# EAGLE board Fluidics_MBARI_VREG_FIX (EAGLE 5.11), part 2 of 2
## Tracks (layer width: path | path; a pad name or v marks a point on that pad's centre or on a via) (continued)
N$52 (continued)
  Top 0.254: R12.1 101.9,63.96 102.55,64.6 103.5,64.6 | 103.82,64.6 IC9.9 103.5,64.6 | R14.2 105.71,64.91 105.41,64.6 103.5,64.6
N$56
  Bottom 0.61: IC1.8 113.86,14.33 115.56,16.03 118.74,16.03 119.69,15.08
  Bottom 1.016: Q4.3 119.69,15.08 120.96,16.35 R81.2
N$57
  Bottom 0.406: C11.2 118.11,32.22
  Bottom 0.61: C11.2 116.84,32.22 116.2,32.86 IC2.8 | D4.1 118.74,29.36 117.79,30.32 117.79,31.9 118.11,32.22
  Bottom 1.27: L3.P$1 113.34,34.44 IC2.8
N$58
  Bottom 0.254: IC4.13 93.02,31.9 93.01,31.89 C3.1
  Bottom 0.406: C3.1 93.02,29.05 93.02,28.09 94.93,26.19 R1.1
N$59
  Bottom 0.305: C1.2 109.53,16.98 107.95,15.39 IC1.5
N$60
  Bottom 0.305: R82.1 105.72,9.68 106.68,8.73 107.95,8.73 IC1.4
N$61
  Bottom 0.254: 130.82,38.56 LED.2
  Bottom 0.305: R0.1 130.82,38.56
N$62
  Bottom 0.305: C11.1 120.33,32.22 120.96,32.86 IC2.1
N$63
  Bottom 0.254: IC12.4 128.9,5.55 128.27,6.18 128.27,7.46 128.9,8.09 | 128.9,8.09 IC12.2 | 128.9,8.09 128.15,8.84 128.27,10.31 129.42,11.47 R49.2 129.47,13.42 129.22,13.81 129.22,16.98 130.17,17.62 130.17,26.51 133.32,29.66 Q8.3
N$64  (via drill 0.61)
  Top 0.254: 140.01,12.22 v138.43,12.22
  Top 0.305: 140.01,12.22 141.28,10.95 v141.28,8.09
  Bottom 0.254: IC11.4 140.01,5.55 140.65,6.18 140.65,7.46 | 140.65,7.46 140.01,8.09 IC11.2 | 140.65,7.46 v141.28,8.09 | 140.39,16.73 140.33,27.78 139.44,28.66 Q9.3
  Bottom 0.305: R48.2 138.17,12.47 v138.43,12.22 138.43,14.76 140.39,16.73
N$66
  Top 0.254: IC7.1 120.33,85.88 C13.2
  Bottom 0.254: C13.2 118.42,86.19 119.69,84.92 119.69,81.75 119.06,81.11 R52.2 119.69,74.45 120.31,75.07 R61.1
N$68
  Top 0.254: IC7.2 120.33,84.61 C13.1 116.84,84.29 R60.1
N$70
  Bottom 0.254: IC5.11 137.16,39.2 139.38,41.43 139.38,42.38 140.01,43.02 | 141.92,43.02 IC5.1 140.01,43.02 | R50.2 140.32,43.32 140.01,43.02
N$71  (via drill 0.61)
  Top 0.254: R59.2 117.47,80.48 114.93,83.02 v114.93,85.24 | IC8.6 111.76,83.02 113.98,85.24 v114.93,85.24 | v114.93,85.24 114.93,85.56 115.55,86.18 R60.2 116.84,90 117.15,90.32 R57.1
N$72
  Top 0.254: IC7.14 129.53,85.88 130.16,86.5 R56.1 130.81,86.51 130.82,86.5 C28.2 133.68,86.5 134.62,85.56 134.62,82.7 R55.2
  Bottom 0.254: R65.1 133.65,81.74 R55.2
N$73
  Top 0.254: 128.27,84.61 IC7.13 | 128.27,84.61 130.81,84.61 | 130.81,84.61 R56.2 | C28.1 130.82,84.62 130.81,84.61 | C27.2 129.22,90 126.36,87.15 126.36,85.24 127,84.61 128.27,84.61
N$74
  Top 0.254: R57.2 120.65,90.32 120.96,90 C27.1
N$75
  Top 0.254: IC7.6 121.28,79.53 120.98,79.83 R58.2 119.68,79.83 117.47,77.62 R59.1
N$77
  Bottom 0.61: D21.2 Q32.3
N$78
  Bottom 0.254: Q31.3 47.94,37.94 47.3,37.3 47.3,36.03
  Bottom 0.406: 47.3,36.03 R116.2 47,34.43 47.3,34.12 47.13,33.95 Q32.1
N$79
  Bottom 0.254: Q31.1 R115.1 48.27,44.29 50.48,44.29 51.43,43.33 51.43,43.02 C34.-
N$80
  Bottom 0.61: D25.2 44.45,29.05 42.86,30.63 Q37.3
N$81
  Bottom 0.61: D24.2 Q36.3
N$82
  Bottom 0.254: Q35.3 37.78,37.94 37.14,37.3 37.14,36.03
  Bottom 0.406: 37.14,36.03 R119.2 36.84,34.43 37.14,34.12 36.97,33.95 Q36.1
N$83
  Bottom 0.254: Q35.1 R118.1 38.11,44.29 40.32,44.29 41.27,43.33 41.27,43.02 C35.-
N$84
  Bottom 0.61: D28.2 34.28,29.05 32.7,30.63 Q41.3
N$85
  Bottom 0.61: D27.2 Q40.3
N$86
  Bottom 0.254: Q39.3 27.62,37.94 26.98,37.3 26.98,36.03
  Bottom 0.406: 26.98,36.03 R122.2 26.68,34.43 26.98,34.12 26.81,33.95 Q40.1
N$87
  Bottom 0.254: Q39.1 R121.1 27.95,44.29 30.16,44.29 31.11,43.33 31.11,43.2 C36.-
N$88
  Top 0.61: D7.2 26.67,29.05 27.62,30 Q13.3
N$89
  Top 0.61: D6.2 Q12.3
N$90
  Top 0.254: Q11.3 33.8,38.11 33.97,37.94 33.97,36.03
  Top 0.406: 33.97,36.03 R101.2 33.64,33.81 33.65,33.81 | 33.65,33.81 | Q12.1 33.65,33.81
N$91
  Top 0.254: Q11.1 33.65,43.65 R100.1 32.37,44.92 30.16,44.92 28.89,43.65 C29.-
N$92
  Top 0.254: D30.1 68.58,58.26 67.04,56.72 R128.1
N$93B
  Top 0.254: U2.6 61.49,70.86 60.95,70.32 59.68,70.32 58.41,71.59 56.51,71.59 C47.1
N$95
  Top 0.254: R90.1 15.23,68.41 16.19,67.46 16.19,66.83 IC16.8
N$98
  Top 0.254: IC16.6 17.78,64.29 18.73,65.24 18.73,69.37 R91.1
N$99B
  Top 0.254: C42.+ 80.45,39.34 82.86,41.74 U5.2
N$100
  Top 0.61: D10.2 36.19,29.05 37.78,30.63 Q17.3
N$101B
  Top 0.254: U5.1 84.77,40.48 84.77,40.16 83.37,38.76 C41.+
N$102B
  Top 0.254: C41.- 86.17,38.7 86.36,38.89 86.36,42.38 85.72,43.02 U5.3
N$103B
  Top 0.254: C43.+ 87.44,41.3 86.99,41.74 86.99,43.65 86.36,44.29 U5.4
N$104B
  Top 0.254: C43.- 87.81,44.1 86.36,45.55 U5.5
N$106
  Top 0.254: IC15.1 23.17,66.83 23.17,67.78 23.81,68.41 R87.2
N$107
  Top 0.254: IC15.6 28.25,64.29 28.27,64.3 R88.1
N$108
  Top 0.61: D9.2 Q16.3
N$109
  Top 0.254: Q15.3 43.96,38.11 44.13,37.94 44.13,36.03
  Top 0.406: 44.13,36.03 R104.2 43.8,33.81 43.81,33.81 | 43.81,33.81 | Q16.1 43.81,33.81
N$110
  Top 0.254: Q15.1 43.81,43.65 R103.1 42.53,44.92 40.32,44.92 39.05,43.65 C30.-
N$111
  Top 0.61: D13.2 45.71,29.05 47.94,31.27
  Top 0.813: 47.94,31.27 Q21.3
N$112
  Top 0.61: D12.2 Q20.3
N$113
  Top 0.254: Q19.3 54.12,38.11 54.29,37.94 54.29,36.03
  Top 0.406: 54.29,36.03 R107.2 53.96,33.81 53.97,33.81 | 53.97,33.81 | Q20.1 53.97,33.81
N$114
  Top 0.254: Q19.1 53.97,43.65 R106.1 52.69,44.92 50.48,44.92 49.52,43.97 49.21,43.97 49.21,43.78 C31.-
N$115
  Top 0.61: D16.2 56.19,29.05 58.1,30.95
  Top 0.813: 58.1,30.95 Q25.3
N$116
  Top 0.61: D15.2 Q24.3
N$117
  Top 0.254: Q23.3 64.28,38.11 64.45,37.94 64.45,36.03
  Top 0.406: 64.45,36.03 R110.2 64.12,34.12 64.13,34.12 | 64.13,34.12 | Q24.1 64.13,34.12
N$118
  Top 0.254: Q23.1 64.13,43.65 R109.1 62.85,44.92 60.95,44.92 59.68,43.65 C32.-
N$122
  Bottom 0.254: R7.2 94.94,29.67 93.66,30.95 93.66,33.17 93.34,33.49
  Bottom 0.406: C3.2 91.13,30.01 91.75,30.63 IC4.14 91.75,33.17 92.07,33.49 93.34,33.49 93.34,35.4 93.02,35.71 IC4.2 93.02,37.62
N$132
  Bottom 0.254: IC4.12 94.29,34.12 | R4.2 99.69,40.48 100.01,40.79 99.68,41.12 C61.1
  Bottom 0.406: R4.2 99.68,38.88 99.37,38.57 IC4.7 99.37,34.76 98.1,33.49 IC4.9 98.1,33.81 97.47,34.44 94.61,34.44 94.29,34.12
N$133  (via drill 0.61)
  Top 0.406: v65.08,8.41 78.1,8.41 v89.85,20.16
  Bottom 0.254: Q6.1 64.76,8.73 v65.08,8.41
  Bottom 0.406: v89.85,20.16 89.85,32.22 91.75,34.44 IC4.1
N$134  (via drill 1.78)
  Bottom 1.27: Q5.2 71.12,15.71 72.54,17.14 | 72.54,17.14 72.7,17.3 L1.P$2 72.7,22.38 v73.66,23.33 | 72.54,17.14 | D2.C 73.66,16.03 72.54,17.14
N$135  (via drill 0.61)
  Top 0.254: v100.58,37.68 99.18,39.08 v96.64,39.08 96.64,39.01 95.23,37.61 C60.2
  Bottom 0.254: IC4.5 96.83,38.89 v96.64,39.08 | 101.59,36.79 101.47,36.79 v100.58,37.68
  Bottom 0.406: IC4.5 96.83,37.62 | R3.1 101.59,36.79 R2.2
N$136
  Bottom 0.254: R4.1 97.8,40.49 C61.2
  Bottom 0.406: R4.1 97.8,39.22 98.1,38.89 IC4.6
N$137
  Bottom 0.406: IC4.10 96.83,31.9 96.82,31.89 R7.1 R6.2
N$138
  Bottom 0.406: R8.1 93.67,39.51 94.29,38.89 IC4.3
N$143
  Bottom 0.254: R39.1 94.93,57.62 94.29,58.26 J2.2
N$144
  Bottom 0.254: 94.93,51.91 R39.2 | R39.2 | 94.93,51.91 95.56,51.27 IC6.2 95.56,50 | R40.1 92.07,50.63 93.34,51.91 94.93,51.91 | R83.2 96.83,58.26 96.2,57.62 96.2,53.49 95.88,53.18 R39.2
N$145
  Bottom 0.254: R43.1 97.16,52.87 97.15,52.86 | 97.15,52.86 R41.2 | IC6.3 96.83,52.54 97.15,52.86
N$146
  Bottom 0.254: R41.1 99.06,53.18 99.39,53.51 R42.1 101.59,52.54 102.55,51.59 J4.2
N$147
  Bottom 0.305: Q7.E 64.91,14.61 66.35,13.17 Q5.1 67,11.91 R5.2 66.35,7.77 65.72,7.14 62.22,7.14 60.95,8.09 D3.A
N$148
  Bottom 0.305: Q7.B 64.91,16.49 63.81,15.39 63.81,12.85 | 63.81,12.85 Q6.3 | 63.81,12.85 62.86,12.85 61.92,11.91 R44.2 60.33,11.91 56.51,8.09 D3.C
NVREF1
  Top 0.254: R89.1 21.26,60.17 24.76,56.67 R84.P$2
NVREF2
  Top 0.254: R92.1 10.14,60.17 13.33,56.98 R85.P$2
P
  Top 0.254: R17.2 129.87,71.58 129.53,71.91 R53.3
  Bottom 0.254: R63.2 127.63,72.86 126.68,71.91 | 125.09,71.91 R53.3 126.68,71.91 | R64.1 127.63,70.95 126.68,71.91
PGC  (via drill 0.61)
  Top 0.254: U1.52 50.27,55.6 v52.38,53.49
  Bottom 0.254: v52.38,53.49 52.7,53.81 54.6,53.81 55.56,52.86 67.62,52.86 69.84,50.95 69.84,46.51 J10.3
PGD  (via drill 0.61)
  Top 0.254: U1.47 51.27,58.1 v53.34,56.03
  Bottom 0.254: v53.34,56.03 53.65,55.72 57.14,55.72 59.37,53.49 67.94,53.49 71.12,50.95 71.12,48.09 J10.4
PIC_RS232_RX_A  (via drill 0.61)
  Top 0.254: 78.73,44.29 U5.13 v80.96,44.29 | v81.28,5.87 v81.28,8.41
  Bottom 0.254: J5.2 78.73,78.26 82.23,74.77 82.23,45.55 v80.96,44.29 80.96,42.7 81.59,42.06 81.59,10.31 81.28,10 v81.28,8.41 | v81.28,5.87 81.28,3.49 P3.34
PIC_RS232_RX_B  (via drill 0.61)
  Top 0.254: U5.8 84.77,49.37 84.77,50.95 v84.45,51.27
  Bottom 0.254: J3.2 88.26,88.42 89.21,87.46 89.21,81.75 84.13,76.67 84.13,51.59 v84.45,51.27
PIC_RS232_TX_A  (via drill 0.61)
  Top 0.254: 78.42,43.02 U5.14 v81.91,43.02 | v80.32,25.87 v82.55,25.87 | P3.33 v80.01,8.41
  Bottom 0.254: J5.3 81.28,87.78 80.01,86.51 80.01,78.26 83.18,75.08 83.18,44.29 v81.91,43.02 82.55,42.38 v82.55,25.87 | v80.32,25.87 80.32,8.73 v80.01,8.41
PIC_RS232_TX_B  (via drill 0.61)
  Top 0.254: 84.45,48.09 U5.7 v86.36,48.09
  Bottom 0.254: J3.3 90.8,88.42 90.17,87.78 90.17,81.11 85.09,76.03 85.09,52.22 85.72,51.59 85.72,48.73 v86.36,48.09
PID_OUT
  Top 0.254: 118.42,53.81 117.15,53.81 116.85,53.51 R20.1 115.56,53.81 117.15,52.22 119.06,52.22 | IC10.2 119.06,60.16 120.01,59.21 120.01,54.13 119.69,53.81 118.42,53.81 | 118.42,53.81 IC10.7 | R22.2 124.76,51.26 124.14,50.63 119.69,50.63 119.06,51.27 119.06,52.22 | 119.06,52.22 R24.2
PRES1_OUT
  Top 0.254: U3.11 38.36,75.66 38.09,75.4 38.09,75.08 30.79,67.78 30.79,66.18 R88.2
PRES2_OUT
  Top 0.254: U3.10 37.74,76.31 31.11,69.68 20.95,69.68 20.63,69.37 R91.2 20.62,69.06 20.63,69.05
PROP  (1 unrouted)
  Top 0.254: R53.2 125.09,74.45 122.61,76.92 IC7.7 121.28,78.26 120.98,77.95 R58.1 120.02,77.95 117.79,75.72 R129.1
  Bottom 0.254: R63.1 126.35,75.39 R53.2
PROP1  (via drill 0.6, 0.61)
  Top 0.254: 38.09,80.8 37.39,81.5 35.94,81.5 31.75,77.3 7.62,77.3 6.03,75.72 P1.53 | 38.09,80.8 U3.3 | v93.66,80.16 94.93,78.89 96.2,78.89 99.06,76.03 101.59,76.03 101.91,75.72 R129.2 113.36,76.36 114.61,77.62 C59.1 | v92.07,84.61 90.8,84.61 88.58,82.38 81.59,82.38 80.32,83.65 76.51,83.65 v72.07,79.21 | v36.51,86.83 v51.11,86.83 | v36.51,80.48 37.78,80.48 38.09,80.8
  Bottom 0.254: R67.1 5.71,75.72 P1.53 | v93.66,80.16 93.66,83.02 v92.07,84.61 | v72.07,79.21 61.91,79.21 60.64,77.94 54.29,77.94 51.11,81.11 v51.11,86.83 | v36.51,80.48 v36.51,86.83
PS_OUT1+
  Top 0.203: 9.24,66.69 9.75,66.18 12.39,66.18 14.93,63.64 20,63.64
  Top 0.254: IC15.3 20.63,64.29 20,63.65 20,63.64 R89.2 | 9.24,66.69 4.36,66.69 3.25,67.8 P1.48
PS_OUT1-
  Top 0.254: IC15.2 22.22,65.56 19.68,68.1 19.68,70.32 19.36,70.64 12.38,70.64 9.84,68.1 P1.47
PS_OUT2+
  Top 0.254: IC16.3 9.52,64.29 8.25,63.02 R92.2 8.25,62.38 6.34,64.29 3.81,64.29 P1.46
PS_OUT2-
  Top 0.254: P1.45 IC16.2
PVDD  (via drill 0.61)  (1 unrouted)
  Top 0.254: U1.71 51.68,50.57 v52.38,51.27 | U1.48 47.07,57.6 | v56.51,57.62 57.03,57.1 U1.12 58.93,57.1 59.68,56.35 | C50.1 47.3,76.35 47.4,76.25 C49.1 47.3,74.45 46.73,75.02 U3.17 | C50.1 47.4,77.2 46.35,78.26 45.08,78.26 45.09,78.27 U3.22 | U1.53 46.01,55.1 46.98,54.13 v46.98,53.18 | 63.49,56.35 63.43,56.29 C39.1 63.56,56.29 63.49,56.35 | 63.49,56.35 63.18,56.67 63.18,57.3 62.86,57.62 61.43,57.62 60.95,57.14 60.95,56.51 60.8,56.35 | 59.68,56.35 | 59.68,56.35 59.84,56.19 60.64,56.19 60.8,56.35 | 60.8,56.35 | D30.2 72,58.51 72,59.4 v71.75,59.84 | 47.06,57.57 47.29,57.44 v47.62,57.18 | v37.14,66.51 37.33,66.59 37.33,67.93 C51.1 37.45,68.11 37.46,68.1 37.67,68.3 U4.14 | C50.1 48,77 48,77.53 v48.25,77.94 51.43,77.94 52.38,76.99 52.38,75.4 53.02,74.77 53.97,74.77 54.6,75.4 IC13.2 | U1.25 54.18,64.18 v54.29,64.29 | v49.52,60.03 49.52,60.16 50.68,61.31 U1.32 | C25.1 55.56,74.13 54.6,75.08 IC13.2 | IC13.2 54.6,76.67 | 78.42,40.48 74.93,40.48 73.66,41.74 J10.2 | 78.42,40.48 U5.16 | C42.- 77.65,38.76 78.42,39.52 78.42,40.48 | R78.1 84.44,55.07 84.77,55.4 84.77,56.35 Q42.2 86.53,56.52 v86.99,56.98
  Top 0.61: J10.2 72,41.74 69.72,39.46 R38.1
  pvdd 0.254: J10.2 74.29,41.74
  Bottom 0.254: 75.56,39.84 C40.+ 75.06,39.71 73.02,41.74 J10.2 72.7,41.74 74.29,43.33 74.29,50.32 70.8,53.81 70.8,58.89 v71.75,59.84 | D34.1 35.55,63.65 37.14,65.24 v37.14,66.51
  pour pvdd (isolate 0.61): 54.6,78.26 36.51,78.26 36.51,43.65 32.38,43.33 68.26,43.33 71.12,46.19 73.97,46.19 73.97,39.52 71.43,39.52 71.43,37.3 88.58,37.3 88.58,63.02 77.47,63.02 77.15,62.7 54.6,62.7
PWM1_IN
  Top 0.254: R95.2 13.95,51.92 13.96,51.91 15.55,53.49 24.12,53.49 26.03,55.4 26.03,57.3 27.62,58.89 32.7,58.89 32.7,60.8 35.87,63.97 39.05,63.97 42.92,60.1 U1.43
PWM1_OUT
  Top 0.254: R95.1 12.07,52.84 11.42,53.49 9.2,53.49 | C53.1 8.67,52.12 8.57,52.22 8.88,52.54 8.88,53.18 9.2,53.49 | P1.38 3.81,56.67 6.98,56.67 9.2,54.45 9.2,53.49
PWM2_IN
  Top 0.254: U1.55 44.79,54.1 44.76,54.13 41.9,54.13 39.68,51.91 24.76,51.91 20.95,48.09 13.65,48.09 13.84,48.29 R96.2
PWM2_OUT
  Top 0.254: R96.1 12.07,47.79 11.42,47.14 9.2,47.14 8.57,47.78 8.57,48.09 8.67,48.2 C54.1 8.76,48.29 8.88,48.41 7.3,50 7.3,53.49 5.39,55.4 P1.37
PWM3_IN  (via drill 0.61)
  Top 0.254: U1.5 56.62,53.6 56.53,53.53 54.93,53.53 54.4,53 v53.97,52.86 | R97.2 16.44,36.92 v17.14,37.62
  Bottom 0.254: v17.14,37.62 17.27,37.74 17.27,38.82 20.19,41.74 22.22,41.74 26.67,46.19 44.13,46.19 50.62,52.69 50.67,52.64 53.69,52.64 v53.97,52.86
PWM3_OUT
  Top 0.254: 8.88,36.66 8.95,36.6 C55.1 | P1.34 2.22,50.32 1.33,49.56 1.33,39.27 1.71,38.89 6.98,38.89 8.95,36.92 C55.1 | C55.1 8.95,36.28 | R97.1 13.98,36.97 13.96,36.98 13.96,37.62 13.65,37.94 12.38,37.94 12.06,38.25 9.2,38.25 8.88,37.3 8.88,37.05 9.01,36.92 C55.1
PWM4_IN  (via drill 0.61)
  Top 0.254: U1.8 57.16,55.1 v56.51,54.45 | R98.2 16.19,43.65 v17.14,43.65
  Bottom 0.254: v56.51,54.45 51.11,54.45 43.49,46.83 24.76,46.83 21.59,43.65 v17.14,43.65
PWM4_OUT
  Top 0.254: 8.57,41.43 8.67,41.53 C56.1 | R98.1 12.07,41.12 11.11,40.16 9.2,40.16 8.88,40.48 8.88,41.43 8.76,41.55 C56.1 | C56.1 8.67,41.64 6.34,43.97 4.12,43.97 3.81,44.29 3.81,51.59 P1.35
PWM5_IN  (via drill 0.61)
  Top 0.254: U1.10 57.21,56.1 56.83,55.72 54.6,55.72 53.97,55.08 52.38,55.08 v52.06,55.4 | v18.73,44.92 18.25,44.73 14.41,44.73 13.96,44.92 14.02,44.87 R99.2
  Bottom 0.254: v18.73,44.92 20.32,44.92 22.86,47.46 42.22,47.46 42.31,47.48 42.49,47.48 47.82,52.82 47.82,53 50.13,55.31 50.16,55.4 v52.06,55.4
PWM5_OUT
  Top 0.254: R99.1 12.14,45.8 11.42,46.51 9.2,46.51 | 9.2,46.51 8.57,45.87 8.57,45.24 8.88,44.92 8.82,44.86 C57.1 | 9.2,46.51 6.98,46.51 6.34,47.14 6.34,53.49 5.71,54.13 3.81,54.13 P1.36
RB0
  Top 0.203: 15.87,33.81 20.95,38.89
  Top 0.254: U1.58 43.55,52.6 40.95,50 25.71,50 20.95,45.24 20.95,38.89 | 15.87,33.81 8.88,33.81 6.34,36.35 3.81,36.35 P1.24
RB1
  Top 0.203: 15.55,34.44 20.32,39.2
  Top 0.254: U1.57 43.1,53.1 40.63,50.63 25.39,50.63 20.32,45.55 20.32,39.2 | 15.55,34.44 9.52,34.44 6.66,37.3 5.39,37.3 P1.23
RB2
  Top 0.254: U1.56 42.65,53.6 40.32,51.27 25.08,51.27 19.68,45.87 19.68,42.38 16.19,38.89 7.93,38.89 6.66,40.16 P1.25
RB4
  Top 0.254: U1.54 41.11,54.6 39.36,52.86 29.84,52.86 29.52,52.54 17.78,52.54 15.23,50 13.65,50 13.01,49.37 13.01,40.16 12.38,39.52 8.25,39.52 6.34,41.43 3.49,41.43 2.54,40.48 P1.26
RC0  (via drill 0.61)
  Top 0.254: U1.36 48.68,62.17 47.94,61.43 v46.98,61.43
  Bottom 0.254: v46.98,61.43 43.81,58.26 40.63,58.26 39.68,57.3 33.02,57.3 28.25,52.54 7.62,52.54 6.34,51.27 6.34,49.05 P1.31
RC1  (via drill 0.61)
  Top 0.254: U1.35 49.18,61.46 v49.21,61.43
  Bottom 0.254: v49.21,61.43 48.89,61.11 48.25,61.11 47.62,60.48 46.98,60.48 42.86,56.35 34.6,56.35 29.84,51.59 13.01,51.59 10.47,49.05 8.88,49.05 6.34,46.51 3.81,46.51 P1.32
RD#
  Top 0.203: U1.27 53.18,64.77 53.65,65.24 54.92,65.24 55.63,64.54 U2.16
RESET#  (via drill 0.61)
  Top 0.254: U1.34 49.68,68.57 50,68.57 50.79,69.37 v51.75,69.37 | U2.4 63.17,71.59 63.18,71.59 63.18,70.64 62.86,70.32 62.86,70 62.22,70 v61.91,69.68
  Bottom 0.254: v61.91,69.68 60.64,69.68 60,69.05 52.06,69.05 v51.75,69.37
RH4  (via drill 0.61)
  Top 0.254: U1.22 55.68,61.55 55.65,61.53 55.29,61.18 v54.87,60.95
  Bottom 0.254: P1.29 6.66,45.24 9.52,48.09 14.28,48.09 17.14,50.95 31.43,50.95 36.19,55.72 43.17,55.72 46.35,58.89 50.16,58.89 51.11,59.84 52.38,59.84 53.34,60.82 54.4,60.82 v54.87,60.95
RH5  (via drill 0.61)
  Top 0.254: U1.21 57.07,62.95 v57.14,63.02
  Bottom 0.254: v57.14,63.02 56.83,62.7 56.83,61.43 55.24,59.84 53.97,59.84 53.34,59.21 52.06,59.21 51.11,58.26 47.3,58.26 46.98,57.94 46.35,57.94 41.27,52.86 35.55,52.86 32.7,50 18.73,50 15.23,46.51 8.88,46.51 6.34,43.97 3.81,43.97 P1.30
RH6  (via drill 0.61)
  Top 0.203: U1.20 56.81,61.1 56.51,60.8 56.51,60.48 54.6,58.57
  Top 0.254: v53.97,58.57 54.6,58.57
  Bottom 0.254: v53.97,58.57 53.02,58.57 51.75,57.3 49.02,57.3 48.89,57.11 47.49,55.72 47.11,55.72 43.17,51.59 36.19,51.59 33.97,49.37 19.36,49.37 14.92,44.92 8.88,44.92 6.66,42.7 P1.27
RH7  (via drill 0.61)
  Top 0.203: U1.19 56.95,60.6 56.95,59.65
  Top 0.254: v56.19,58.89 56.95,59.65
  Bottom 0.254: v56.19,58.89 54.29,56.98 52.7,56.98 52.38,56.67 49.21,56.67 43.49,50.95 36.51,50.95 34.28,48.73 20.63,48.73 13.33,41.43 3.49,41.43 2.54,42.38 P1.28
RJ0
  Top 0.203: U1.62 47.18,48.93 46.03,47.78 | 17.46,31.27 23.49,37.3
  Top 0.254: 46.03,47.78 27.3,47.78 23.49,43.97 23.49,37.3 | P1.20 2.99,32.5 3.74,31.43 3.96,31.43 4.12,31.27 17.46,31.27
RJ1
  Top 0.203: 45.77,48.35 46.65,49.24 U1.61 | 17.14,31.9 22.86,37.62
  Top 0.254: 45.77,48.35 26.92,48.35 22.86,44.29 22.86,37.62 | 17.14,31.9 5.71,31.9 P1.19
RJ2
  Top 0.203: 17.98,33.69 22.22,37.94
  Top 0.254: U1.60 44.39,51.6 41.68,48.88 26.5,48.88 22.22,44.6 22.22,37.94 | 17.98,33.69 17.98,33.67 17.95,33.67 16.82,32.54 7.62,32.54 6.34,33.81 4.44,33.81 3.17,35.08 P1.22
RJ3
  Top 0.203: 16.51,33.17 21.59,38.25
  Top 0.254: U1.59 43.99,52.08 41.27,49.37 26.03,49.37 21.59,44.92 21.59,38.25 | 16.51,33.17 7.93,33.17 6.34,34.76 5.39,34.76 P1.21
RSTOUT#
  Top 0.254: U2.5 62.29,72.15 60.95,73.49 R86.2
RXF#
  Top 0.203: U1.30 51.68,65.17 54.29,67.78 58.41,67.78
  Top 0.254: 58.41,67.78 58.45,67.75 U2.12
SER_RX2
  Top 0.254: R78.2 81.11,55.57 Q43.3 74.61,57.94 73.66,56.98 73.66,55.72 | 73.66,55.4 D5.2 73.66,55.72 | U1.7 70.95,54.6 72.07,55.72 73.66,55.72
SER_RX2B
  Top 0.254: U5.9 76.83,49.37 74.29,51.91 73.66,51.91 D5.1
SER_TX1  (via drill 0.61)
  Top 0.254: U1.37 48.18,63.9 49.21,64.92 49.21,67.46 49.17,67.5 49.17,69.02 50.29,70.14 v50.48,70.64 | U5.11 79.69,46.83 80.32,47.46 v80.32,50.95
  Bottom 0.254: v50.48,70.64 50.79,70.95 52.38,70.95 53.34,70 59.37,70 60.64,71.27 65.4,71.27 70.16,66.51 70.16,65.56 73.34,62.38 74.29,62.38 80.32,56.35 v80.32,50.95
SER_TX2  (via drill 0.61)
  Top 0.254: v75.56,48.09 U5.10 | U1.6 72.99,54.1 v75.56,54.13 79.69,54.13 81.28,52.54 82.86,52.54 83.5,52.86 83.5,55.08 82.87,55.71 Q42.1
  Bottom 0.254: 75.56,47.78 v75.56,48.09 v75.56,54.13
SG  (via drill 0.61)
  Top 0.254: U1.38 47.68,64.98 v48.25,65.56 | U5.12 80.01,45.55 v81.28,46.83
  Bottom 0.254: v48.25,65.56 48.57,65.56 51.43,68.41 60.95,68.41 62.22,67.14 66.04,67.14 79.05,54.45 79.05,51.91 79.05,49.05 v81.28,46.83
SI/WU
  Top 0.254: 50.18,63 50.16,63.02 | U1.33 50.18,63 | 50.18,63 50.18,64.62 54.09,68.54 U2.11
SPI_CLK  (via drill 0.61)
  Top 0.254: v40.63,70.95 40.58,70.9 U4.10 38.46,70.9 38.09,71.27 38.09,72.22 38.41,72.54 41.9,72.54 43.73,74.36 U3.16 | U1.44 42.15,59.6 v41.27,60.48
  Bottom 0.254: v40.63,70.95 41.59,70 41.59,64.92 44.13,62.38 44.13,61.43 43.17,60.48 v41.27,60.48
SPI_PIC_DIN  (via drill 0.61)
  Top 0.254: U1.45 45.61,59.1 46.03,59.52 46.03,62.7 43.17,65.56 v43.17,65.88 | U3.15 45.12,72.9 44.45,72.22 43.17,72.22 v42.86,71.91
  Bottom 0.254: v42.86,71.91 42.54,71.59 42.54,66.51 v43.17,65.88
SPI_PIC_DOUT  (via drill 0.61)
  Top 0.203: 37.84,70.25 U4.11
  Top 0.254: U3.19 45.08,76.35 44.45,76.35 41.27,73.18 38.09,73.18 37.46,72.54 37.46,71.27 v37.14,70.95 37.84,70.25 | U1.46 43.84,58.6 43.49,58.26 42.22,58.26 39.36,61.11 39.36,62.38 v39.05,62.7
  Bottom 0.254: v39.05,62.7 38.41,63.34 38.41,64.6 38.35,64.6 38.35,69.81 38.29,69.81 v37.14,70.95
SW1_NEG
  Bottom 0.406: 11.74,7.77 10.79,6.82 10.79,6.5 10.15,5.87 D31.2
  Bottom 0.813: Q1.2 13.65,5.87 11.74,7.77 9.84,9.68 P1.1
SW2_NEG
  Bottom 0.406: 23.17,10.95 3.81,10.95 P1.2 | 21.27,5.23 D32.2 25.08,5.23
  Bottom 0.813: Q2.2 25.08,5.23 25.08,9.04 23.17,10.95
SW3_NEG
  Bottom 0.406: 36.51,5.23 D33.2
  Bottom 0.813: Q3.2 36.51,5.23 36.51,7.46 31.75,12.22 P1.3
TC_SETPOINT  (via drill 0.61)
  Top 0.254: U3.12 40.25,75.02 v40.63,75.4 | J6.2 79.05,70.32 78.42,70.95 v78.42,73.81
  Bottom 0.254: v40.63,75.4 51.11,75.4 53.34,73.18 55.24,73.18 57.14,75.08 77.47,75.08 v78.42,73.81
TC_SETPOINT_SET  (via drill 0.61)
  Top 0.254: U4.2 45.84,67.65 46.35,67.14 46.35,66.83 45.71,66.19 v45.71,64.92 | R19.2 84.45,74.77 82.55,72.86 J6.3
  Bottom 0.254: v45.71,64.92 45.71,67.14 46.35,67.78 47.62,67.78 48.89,69.05 48.89,71.59 49.52,72.22 52.38,72.22 53.34,71.27 59.37,71.27 60.32,72.22 80.01,72.22 J6.3
TC_THERMISTOR  (via drill 0.61)
  Top 0.254: U3.13 40.4,74.36 v40.63,74.13 | v75.56,74.13 76.83,74.13 77.47,73.18 77.47,68.73 78.42,67.78 J6.1 91.44,67.78 92.7,69.37 92.7,70.32 93.66,71.27 v93.66,71.59 | IC9.14 104.77,70.95 105.41,70.32 | 103.5,69.68 IC9.13 104.77,69.68 105.41,70.32 | 105.41,70.32 106.04,70.95 v106.04,71.59
  Bottom 0.254: v40.63,74.13 45.08,74.13 46.03,73.18 52.38,73.18 53.02,72.54 55.56,72.54 57.14,74.13 75.24,74.13 v75.56,74.13 | v93.66,71.59 v106.04,71.59
TCIMON  (via drill 0.61)
  Top 0.254: 123.82,61.43 IC10.14 124.14,61.43 | 124.14,61.43 125.09,61.43 125.4,61.73 R11.1 129.52,61.73 129.53,61.75 R27.2 | U3.8 | U3.8 35.86,77.61 33.02,74.77 9.84,74.77 5.71,70.64 P1.49 | U3.8 41.26,77.61 v42.54,78.89 | v49.84,84.29 50.48,84.29 51.11,84.92 60.95,84.92 63.81,87.78 68.58,87.78 71.75,84.61 80.64,84.61 81.91,83.34 87.31,83.34 93.98,90 v94.61,90 | v104.14,73.49 112.39,73.49 v113.98,71.91 | v124.14,64.92 124.14,61.43
  Bottom 0.254: R47.1 7.3,69.05 5.71,70.64 P1.49 | v42.54,78.89 43.49,79.84 45.4,79.84 v49.84,84.29 | v94.61,90 97.47,90 100.33,87.15 100.33,77.3 v104.14,73.49 | v113.98,71.91 120.33,65.56 123.5,65.56 v124.14,64.92
TEC+  (via drill 0.61)
  Top 0.61: v134.93,5.55 134.93,4.92 133.98,3.96 129.53,3.96
  Top 0.813: 129.53,3.96 127,0.79 44.76,0.79 42.54,3.01 v42.54,8.73
  Bottom 0.61: v134.93,5.55 IC11.5 | 8.88,14.76 6.34,17.3 P1.7
  Bottom 0.813: v42.54,8.73 39.36,8.73 33.33,14.76 8.88,14.76
TEC-
  Bottom 0.406: 3.81,16.03 6.03,16.03
  Bottom 0.61: IC12.5 123.5,5.55 122.87,6.18 84.45,6.18 83.5,7.14 78.73,7.14 78.1,6.5 40,6.18 | 6.03,16.03 8.57,13.49 | P1.8 3.81,16.03
  Bottom 0.813: 40,6.18 32.7,13.49 8.57,13.49
THERMIST+  (via drill 0.61)
  Top 0.254: R29.2 100.63,87.13 99.69,86.19 99.69,84.92 100.33,84.29 IC8.2 102.87,84.29 104.14,83.02 104.14,79.84 C19.2 | v106.36,69.37 106.04,69.37 105.09,68.41 IC9.12
  Top 0.305: P1.4 2.85,12.22 4.12,13.49 49.52,13.49 51.11,15.08 57.14,15.08 60.32,18.25 60.32,20.79 62.22,22.7 68.58,22.7 73.66,27.78 103.82,27.78 v110.17,34.12
  Bottom 0.254: R31.1 109.85,79.53 109.22,80.16 104.45,80.16 C19.2 102.87,76.99 107.47,72.38 107.47,70.48 106.2,69.21 | 108.26,42.7 108.26,67.78 106.83,69.21 106.2,69.21 | 106.2,69.21 v106.36,69.37
  Bottom 0.305: v110.17,34.12 110.17,40.79 108.26,42.7
THERMIST-  (via drill 0.61, 1.02)
  Top 0.305: P1.6 3.81,16.03 6.98,16.03 8.57,14.44 49.21,14.44 50.79,16.03 56.83,16.03 59.37,18.57 59.37,21.11 61.59,23.33 67.94,23.33 73.34,28.73 102.87,28.73 v111.12,36.98
  Bottom 0.254: 109.22,43.02 v109.22,70.64 109.22,71.91 110.48,73.18 R37.1
  Bottom 0.305: v111.12,36.98 111.12,41.11 109.22,43.02
TMP1
  Top 0.254: U6.3 19.68,82.7 19.05,83.34 9.52,83.34 6.98,80.8 P1.57
  Bottom 0.254: R69.1 5.71,80.8 P1.57
TMP2
  Top 0.254: U6.5 22.22,83.02 21.27,83.97 8.88,83.97 6.98,82.07 3.81,82.07 P1.58
  Bottom 0.254: R72.1 6.34,83.97 6.34,82.7 5.71,82.07 3.81,82.07 P1.58
TMP3
  Top 0.254: U6.10 22.22,86.19 20.95,84.92 6.66,84.92 P1.59
  Bottom 0.254: R70.1 6.98,87.78 5.08,85.88 P1.59
TMP4
  Top 0.254: U6.12 19.68,86.19 19.36,85.88 3.81,85.88 2.54,84.61 P1.60
  Bottom 0.254: R71.1 6.66,90.32 6.34,90 6.34,88.1 2.54,84.29 P1.60
TSET
  Top 0.203: 86.34,75.72 86.36,75.72 86.67,75.4 C62.2
  Top 0.254: IC8.3 99.69,83.02 98.74,83.97 R33.3 93.34,83.97 86.36,76.99 86.34,75.72 R19.1
TXE#
  Top 0.203: U1.29 52.18,65.04 53.65,66.51 55.56,66.51 55.93,66.13 U2.14
  Top 0.254: 58.41,66.19 58.45,66.16 U2.14
U5
  Top 0.254: R32.1 105.08,86.52 106.04,85.56 IC8.8 107.31,85.56
USB_P2
  Bottom 0.254: R126.2 64.11,81.41 64.77,82.07 66.67,82.07 67.31,82.7 67.31,84.29 67.36,84.23 P2.2
USB_P3
  Top 0.254: P2.3 66.93,86.14 66.04,85.24 66.04,83.34 65.4,82.7 62.54,82.7 61.3,81.46 R127.2
USB_PWR_RAW
  Bottom 0.254: F1.1 69.55,86.17 68.26,87.46 66.35,87.46 66.04,87.15 66.04,84.61 65.72,84.29 65.4,84.29 65.08,83.97 64.92,84.14 P2.1 62.38,84.14 62.22,84.29 C8.2
USBDM  (via drill 0.61)
  Top 0.254: U2.8 59.89,72.97 58.73,74.13 58.73,78.57 59.39,78.92 59.39,79.18 v59.37,79.21
  Bottom 0.254: v59.37,79.21 59.37,80.48 60.32,81.43 61.59,81.43 61.56,81.41 R126.1
USBDP
  Top 0.254: U2.7 60.57,72.1 60.57,73.24 59.37,74.45 59.37,76.35 59.68,76.67 61.27,76.67 | 61.27,76.67 R86.1 | R127.1 61.3,79.23 61.27,77.94 61.27,76.67
USBPWR  (via drill 0.61)
  Top 0.254: U2.13 59.89,66.93 v60,66.83 | v63.81,70 63.89,70.08 U2.3 63.89,72.78 63.49,73.18 IC17.8 | U2.26 65.94,65.34 v65.4,65.88 | R125.1 64.51,79.91 v65.08,80.48 66.99,80.48 67.62,79.84 67.62,79.21 67.94,78.89 R93.1
  pvdd 0.406: v60,66.83 64.45,66.83 v65.4,65.88
  Bottom 0.254: F1.2 69.55,83.36 67.94,80.48 v65.08,80.48
  pour pvdd (isolate 0.406): 69.53,81.11 69.53,63.97 62.86,63.97 62.86,81.11
V_SUPPLY_NEGATIVE
  Top 0.254: C44.- 87.18,47.33 86.67,46.83 U5.6 84.45,46.83
VALVE1_CTRL  (via drill 0.61)
  Top 0.254: U1.72 52.18,47.89 v51.75,47.46
  Bottom 0.254: Q26.1 62.23,40.47 62.22,40.48 64.58,42.83 C33.+ 63.62,43.52 63.62,44.03 62.22,44.03 59.05,47.21 52.19,47.21 v51.75,47.46
VALVE2_CTRL  (via drill 0.61)
  Top 0.254: U1.68 50.18,46.21 v49.84,45.87
  Bottom 0.254: Q30.1 52.07,40.47 52.06,40.48 54.42,42.83 C34.+ | C34.+ 53.45,43.55 | v49.84,45.87 50.29,45.68 53.46,45.68 53.46,43.52 C34.+
VALVE3_CTRL  (via drill 0.61)
  Top 0.203: U1.66 49.18,47.75 v46.67,45.24
  Bottom 0.254: Q34.1 41.91,40.47 41.9,40.48 44.26,42.83 C35.+ 45.21,43.52 46.1,44.41 46.1,44.54 v46.67,45.24
VALVE4_CTRL  (via drill 0.61)
  Top 0.203: U1.64 48.18,48.66 45.71,46.19
  Top 0.254: 45.71,46.19 37.14,46.19 v36.13,45.17
  Bottom 0.254: Q38.1 31.75,40.47 31.75,40.48 34.1,42.83 C36.+ 35.05,43.52 35.55,44.03 35.55,44.54 v36.13,45.17
VALVE5_CTRL
  Top 0.203: U1.63 47.68,48.79 45.71,46.83
  Top 0.254: 26.03,43.97 26.22,43.78 C29.+ | Q10.1 28.57,40.47 28.57,40.48 26.22,42.83 C29.+ | C29.+ 26.35,43.65 | 45.71,46.83 35.87,46.83 34.6,45.55 27.94,45.55 26.22,43.84 C29.+
VALVE6_CTRL
  Top 0.203: U1.65 48.68,48.52 45.71,45.55
  Top 0.254: Q14.1 38.41,40.91 36.18,43.14 C30.+ | C30.+ 36.19,43.65 | C30.+ 36.51,43.65 38.41,45.55 45.71,45.55
VALVE7_CTRL
  Top 0.254: Q18.1 48.57,40.91 46.34,43.14 C31.+ 46.54,43.84 49.68,46.98 U1.67
VALVE8_CTRL
  Top 0.254: U1.69 50.68,45.99 51.11,45.55 53.97,45.55 55.24,44.29 55.65,44.29 55.82,44.11 C32.+ 56.71,43.22 56.71,43.04 56.73,42.93 59.18,40.48 59.05,40.35 Q22.1
VALVE_1_POWER
  Bottom 0.61: D19.1 60.84,26.62 60.95,26.51 D20.1 59.68,26.51 58.67,25.49 | 58.67,25.49 58.41,25.23 | 58.67,25.49 58.41,25.74 D18.1 58.1,23.96 57.46,23.33 49.21,23.33 47.3,21.43 25.08,21.43 22.54,23.96 9.2,23.96 P1.9
VALVE_2_POWER
  Bottom 0.61: D22.1 51.32,26.62 51.43,26.51 D23.1 49.52,26.51 48.51,25.49 | 48.51,25.49 48.25,25.23 | 48.51,25.49 48.25,25.74 D21.1 47.94,24.28 46.03,22.38 25.71,22.38 22.86,25.23 7.93,25.23 P1.11
VALVE_3_POWER
  Bottom 0.61: D25.1 41.16,26.62 41.27,26.51 D26.1 39.36,26.51 38.09,25.23 37.89,25.44 D24.1 | D24.1 37.78,25.55 | D24.1 37.78,24.28 36.82,23.33 26.35,23.33 23.17,26.51 6.66,26.51 P1.13
VALVE_4_POWER
  Bottom 0.61: D28.1 31,26.62 31.11,26.51 D29.1 29.21,26.51 28.19,25.49 | 28.19,25.49 27.94,25.23 | 28.19,25.49 27.94,25.74 27.67,25.49 | 27.67,25.49 D27.1 | P1.15 23.17,27.46 23.81,28.09 25.08,28.09 27.67,25.5 27.67,25.49
VALVE_5_POWER
  Top 0.406: 3.81,28.73 20.63,28.73
  Top 0.61: 30.16,26.51 31.43,26.51 32.16,25.78 | 32.16,25.78 32.49,25.44 | 30.16,26.51 D8.1 | D7.1 29.95,26.71 30,26.66 | 30,26.66 30.16,26.51 | 32.16,25.78 32.7,25.36 D6.1 32.7,25.55 | P1.16 3.81,28.73 | 20.63,28.73 24.44,24.92 29.21,24.92 29.84,25.55 29.84,26.51 30,26.66 | 30,26.66
VALVE_6_POWER
  Top 0.406: 3.81,26.19 6.34,26.19
  Top 0.61: D10.1 39.48,28.84 39.36,28.73 39.48,28.62 D11.1 | D11.1 38.82,26.28 | D11.1 39.68,26.51 40.75,25.44 D9.1 42.86,25.23 40.95,23.33 24.44,23.33 20.32,27.46 7.62,27.46 6.34,26.19 | P1.14 3.81,26.19
VALVE_7_POWER
  Top 0.406: 4.12,23.65 6.03,23.65
  Top 0.61: D13.1 48.89,29.05 49,28.93 D14.1 | D14.1 52.06,26.51 52.57,26 | 53.02,25.55 52.57,26 | D14.1 48.37,26.28 | 52.57,26 52.7,26.12 D12.1 53.02,25.55 | 53.02,25.55 51.75,24.28 47.94,24.28 46.03,22.38 23.81,22.38 20,26.19 8.57,26.19 6.03,23.65 | P1.12 2.85,22.38 4.12,23.65
VALVE_8_POWER
  Top 0.406: 3.81,21.11 5.71,21.11
  Top 0.61: D17.1 59.68,26.51 59.8,26.62 D16.1 | D17.1 62.54,26.51 62.95,26.09 | 62.95,26.09 63.18,25.87 | D17.1 59.14,26.28 | 62.95,26.09 62.99,26.12 D15.1 63.18,24.92 62.86,24.6 57.78,24.6 56.51,23.33 48.89,23.33 46.98,21.43 23.17,21.43 19.68,24.92 9.52,24.92 5.71,21.11 | P1.10 3.81,21.11
VBAT  (via drill 0.61)
  Top 0.254: IC3.2 134.44,27.61 133.98,27.14 133.98,22.38 134.62,21.74 134.62,19.52 133.98,18.89 133.98,8.73
  Top 0.305: 133.98,8.73 136.52,6.18 136.52,3.33 135.25,2.06 R30.2 | R80.2 124.3,2.22 125.89,2.22 v126.04,2.06
  Bottom 0.305: 126.04,3.33 v126.04,2.06
  Bottom 0.406: 119.06,3.45 122.23,3.45
  Bottom 0.61: P3.3 118.11,4.6 119.06,3.45
  Bottom 0.813: R30.2 128.58,2.06 127.31,3.33 126.68,3.33 | 122.23,3.45 126.04,3.33 126.68,3.33 | C58.1 127.95,17.62 127.63,17.3 127.63,11.9 126.68,10.95 126.68,3.33
VBAT-2
  Top 0.254: IC3.1 137.33,27.61 137.79,27.14 137.79,16.66
  Top 0.305: 137.79,16.66 137.16,16.03 137.16,9.36 140.33,6.18 R30.1
  Bottom 1.778: L2.P$1 144.14,5.87 R30.1
VCONT
  Bottom 0.305: R40.2 95.87,47.16 96.83,46.19 IC6.6 96.83,44.92 | 96.83,44.92 96.83,44.6 | 96.83,44.92 96.83,44.29 95.55,43
  Bottom 0.406: R8.2 95.55,43
VFB
  Top 0.254: R51.1 98.1,60.8 99.69,59.21 R28.1 | J4.3 104.14,56.35 102.87,57.62 100.96,57.62 100.33,58.26 R28.1 | R28.1 | J2.3 93.66,60.8 95.25,59.21 96.83,59.21 97.47,59.84 97.47,60.48 R51.1 | R51.1
VREF  (via drill 0.61)  (3 unrouted)
  Top 0.254: 98.74,87.78 R29.1 | R16.1 100.63,89.67 98.74,87.78 | 95.56,72.86 v92.39,72.86 88.9,72.86 C23.+ | 95.56,72.86 R35.2 95.58,73.19 95.88,73.49 96.86,74.46 96.86,75.69 95.88,76.67 VR2.5 | 95.56,72.86 95.71,73.01 | 98.74,87.78 98.1,87.15 v98.1,86.19
  pvdd 0.406: v11.42,80.16 12.38,80.16 13.65,78.89 32.06,78.89 37.33,84.16 45.84,84.16 47.94,81.75 52.06,81.75 52.7,82.38 59.24,82.57 59.75,82.07 83.81,82.07 v92.39,72.86
  Bottom 0.254: R69.2 9.52,82.7 | R69.2 9.51,85.23 9.52,85.24 R72.2 R70.2 9.52,87.78 R70.2 R71.2 | R69.2 R73.2 9.52,80.16 9.52,77.62 | 9.52,77.62 R68.2 | R68.2 9.52,77.62 | R73.2 v11.42,80.16 | v98.1,86.19 98.1,78.57 v92.39,72.86 92.39,66.19 R34.1
VREF-
  Top 0.254: 98.1,70.95 95.88,70.95 R34.2 | R36.1 99.7,73.19 99.69,71.27 99.37,70.95 98.1,70.95 | 98.1,70.95 IC9.1
VSWREG  (via drill 0.61, 1.78)
  Top 0.305: C4.1 97.15,23.96 98.42,25.23 104.77,25.23 v109.53,30
  Top 0.813: 109.85,10 114.93,10 118.11,6.82 121.6,6.82 122.55,5.87 130.17,5.87 v131.76,7.46
  Top 1.27: C4.1 109.85,10
  Bottom 0.305: v109.53,30 109.53,31.9 109.22,32.22 109.22,40.16 107.31,42.06 107.31,54.13 103.18,58.26 R83.1
  Bottom 0.61: IC11.3 137.47,6.82 136.52,5.87 136.52,4.92 135.88,4.28 132.39,4.28 131.76,4.92 131.76,6.5 131.44,6.82 IC12.3
  Bottom 0.813: v131.76,7.46 131.76,7.14 131.44,6.82
  Bottom 1.27: v85.09,8.41 85.09,10.95 L1.P$1 85.4,11.58 89.53,15.71 91.12,15.71 | 91.44,15.71 C9.2 91.12,15.71 | C4.1 95.88,22.7 91.12,17.93 91.12,15.71
WR
  Top 0.203: 52.7,63.02 52.7,64.92 53.65,65.88 55.24,65.88 55.78,65.34 U2.15
  Top 0.254: 52.7,63.02 52.68,63 U1.28

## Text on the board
tNames: OFS | D | P | I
